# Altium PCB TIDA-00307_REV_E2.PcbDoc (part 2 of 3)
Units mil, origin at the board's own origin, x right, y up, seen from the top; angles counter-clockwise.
Board outline 2360 x 3725 mil, 4 copper layers (Top Layer, L2_GND-PLANE, L3_PWR-PLANE, Bottom Layer), stack 90 mil thick; 312 components, 149 nets, 674 pads, 257 vias.
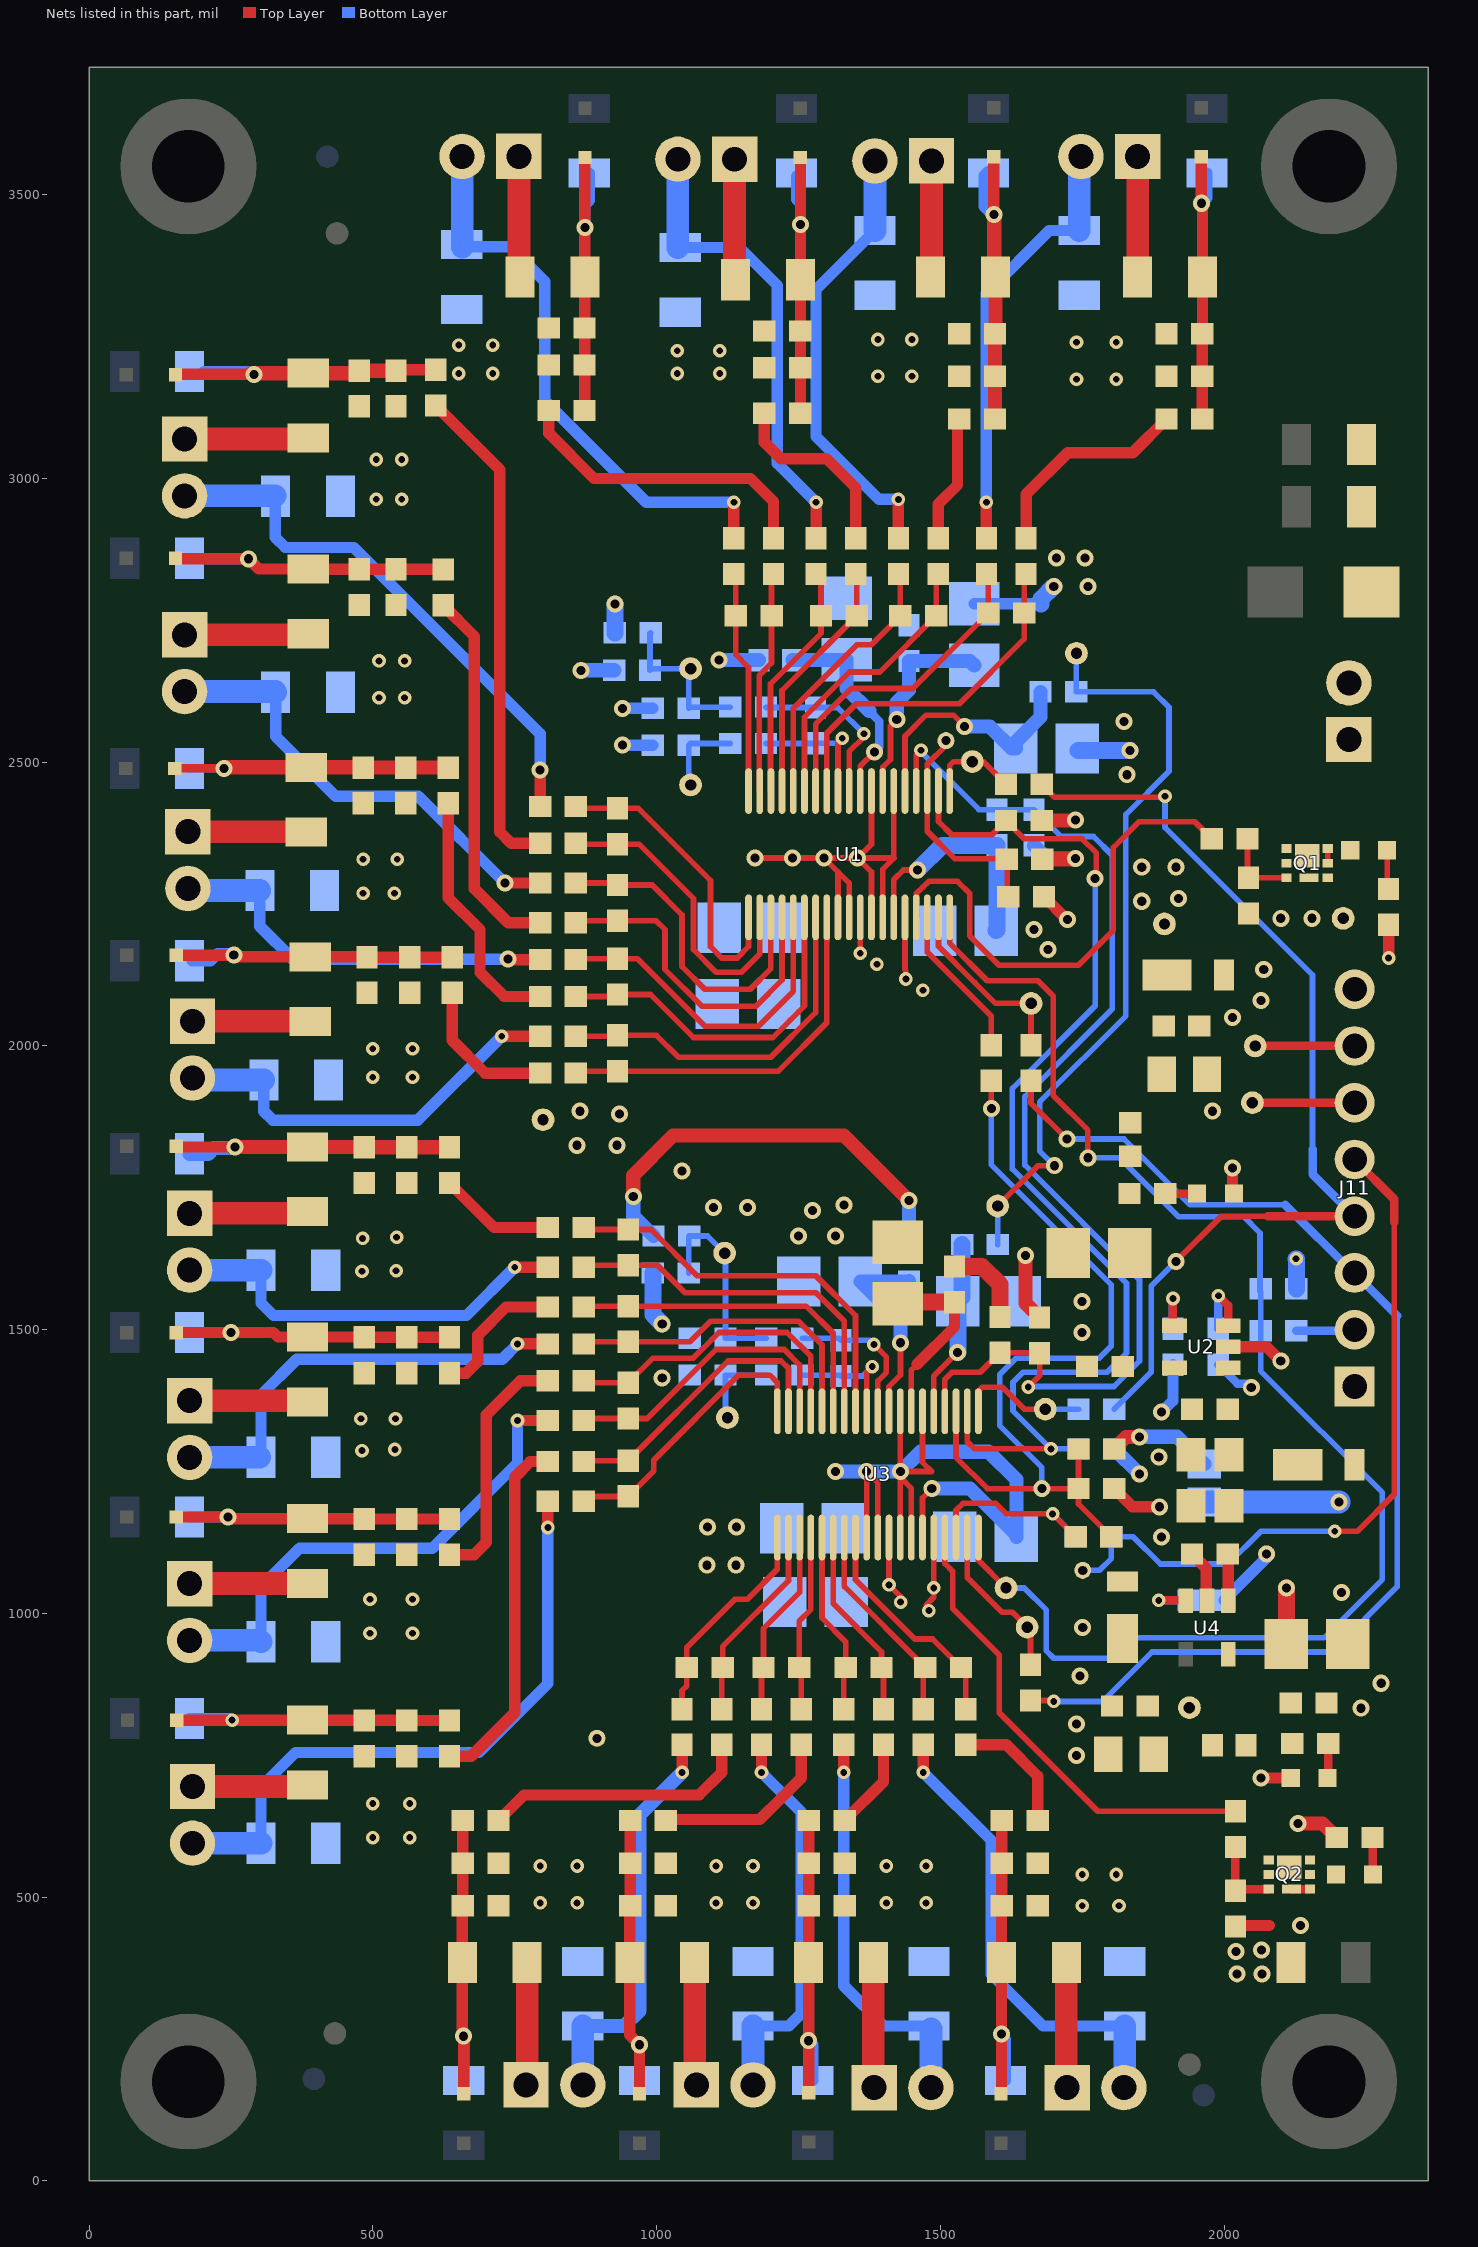
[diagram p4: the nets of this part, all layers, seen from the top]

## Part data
C1 C2: "CAP, CERM, 1000pF, 2KV 10% X7R 1206"
C3 C4 C5 C6 C7 C8 C10 C12 C14 C17 C20 C22 C26 C27 C28 C29 C45 C56: "CAP, CERM, 0.01uF, 100V, +/-5%, X7R, 0603"
C9 C34: "CAP, CERM, 0.1uF, 25V, +/-5%, X7R, 0603"
C11 C19 C21 C25 C31 C32: "CAP, CERM, 0.1uF, 50V, +/-10%, X7R, 0603"
C13 C33: "CAP, CERM, 4.7uF, 50V, +/-10%, X5R, 0805"
C15 C43: "CAP, CERM, 1uF, 16V, +/-10%, X7R, 0603"
C16 C18 C30 C41 C42 C46 C48 C49 C50 C52 C54 C58 C59 C60: library part 293D106X9016B2TE3, "CAP, TA, 10 µF, 16 V, +/- 10%, 2 ohm, SMD"
C23 C24: "CAP, CERM, 1uF, 50V, +/-10%, X7R, 0805"
C35 C36 C37 C38 C39 C40 C44 C47 C51 C53 C57 C61 C62 C63 C64 C65: "CAP, CERM, 0.027uF, 50V, +/-5%, C0G/NP0, 1206"
C55: "CAP, CERM, 0.01uF, 50V, +/-5%, X7R, 0603"
D1 D2 D3 D4 D5 D6 D8 D10 D12 D14 D16 D18 D21 D22 D23 D24: library part CDSOD323-T15SC, "Diode, TVS, ARRAY, 19V, SOD323"
D7: "TVS 18 VOLT 600 WATT BI-DIR SMB"
D9 D13 D19 D20: "LED SmartLED Green 570NM"
D11 D17: "DIODE ZENER 5.9V 1W PMDS"
D15: "Diode, Schottky, 200V, 1A, PowerDI123"
FB1 FB2 FB3 FB4: library part MMZ1608B102C, "FERRITE CHIP 1000 OHM 300MA 0603"
FID1 FID2 FID3 FID4 FID5 FID6: library part Fiducial40_0
H1 H2 H3 H4: "Machine Screw, Round, #4-40 x 1/4, Nylon, Philips panhead"
J1 J2 J3 J4 J5 J6 J7 J8 J9 J10 J12 J13 J14 J15 J16 J17 J18: "Terminal Block, 4x1, 2.54mm, TH"
J11: "Terminal Block, 8x1, 2.54 mm, TH"
LBL1: library part THT-14-423-10, "Thermal Transfer Printable Labels, 0.650\" W x 0.200\" H - 10,000 per roll"
Logo1: library part TI_Logo, "Texas Instrument Corporate Signature"
Q1 Q2: "MOSFET, N-CH, 30V, 22A, SON 2X2 MM"
R1 R2 R3 R4 R19 R29 R36 R48 R57 R69 R80 R94 R111 R112 R113 R114: "RES 100 OHM .4W 1% 0204 MELF"
R5 R6 R7 R8 R9 R11 R13 R15 R17 R20 R30 R32 R37 R42 R52 R53 R59 R60 R71 R72 R81 R82 R95 R96 R102 R103 R104 R105 R107 R108 R109 R110: library part CRCW060322R0JNEA, "RES, 22 ohm, 1%, 0.1W, 0603"
R10 R12 R14 R16 R18 R31 R38 R49 R61 R73 R78 R83 R97 R98 R99 R100: "RES, 1.00k ohm, 1%, 0.1W, 0603"
R21 R23 R24 R26 R33 R44 R46 R50 R63 R66 R70 R74 R85 R87 R89 R91: "RES, 1.6k ohm, 5%, 0.1W, 0603"
R22 R25 R27 R28 R34 R39 R43 R51 R54 R55 R56 R62 R64 R65 R75 R79 R84 R86 R88 R90 R92 R123 R124 R127 R131 R134 R135 R138 R140 R143: library part RC0402JR-070RL, "RES, 0 ohm,5%, 0.1W, 0603"
R35 R40 R45 R67 R68 R76 R77 R126 R128 R133 R142 R154 R155 R156 R157: library part RT0603BRD0747KL, "RES, 47.0k ohm, 1%, 0.1W, 0603"
R41 R47 R101 R106: "RES, 300 ohm, 5%, 0.1W, 0603"
R58 R93: "RES, 560 ohm, 5%, 0.1W, 0603"
R115 R116 R117 R118 R119 R120 R121 R129 R130 R132 R141 R146 R147 R148 R149 R150 R151: library part RC0402JR-070RL, "RES, 0 ohm,5%, 0.25W, 1206"
R122 R125 R136 R139: "RES, 357 ohm, 1%, 0.1W, 0603"
R137 R145: "RES, 10.0k ohm, 1%, 0.1W, 0603"
R144: library part RC0402JR-070RL, "RES, 0 ohm,5%, 0.125W, 0805"
TP1 TP2 TP3 TP4 TP5 TP6 TP7 TP8 TP9 TP10 TP11 TP12 TP13 TP14 TP15 TP16 TP17 TP18 TP19 TP20 TP21 TP22 TP23 TP24: library part TP-040_RND, "Test Point 40mil pad 20mil drill"
U1 U3: "16 bit 400KSPS 8 Channel SAR ADC"
U2: "IC REG LDO 5V 0.15A SOT23-5"
U4: "IC REG LDO 3.3V 0.15A SOT23-5"
ZZ1: library part AssemblyNoteLabel
ZZ2 ZZ3 ZZ4: library part AssemblyNote

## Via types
v1: diameter 30, hole 16, Top Layer to Bottom Layer, tented both sides, 155 vias
v2: diameter 24, hole 12, Top Layer to Bottom Layer, tented both sides, 102 vias

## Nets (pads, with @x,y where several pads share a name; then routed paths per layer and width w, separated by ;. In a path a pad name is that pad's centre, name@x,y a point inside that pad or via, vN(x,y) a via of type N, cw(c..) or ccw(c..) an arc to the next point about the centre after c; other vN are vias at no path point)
2AIN0: R65.1 R78.2 | length 482.3
  Top Layer w20: R78.2@635,1103.5 678.5,1103.5 700,1125 ; 700,1175 700,1125 ; R65.1@808.5,1410 760,1410 700,1350 700,1125
2AIN1: R75.1 R83.2 | length 631.7
  Top Layer w20: R83.2@635,748.5 673.5,748.5 750,825 750,885 750,1240 777.73,1267.73 R75.1@808.5,1267.73
2AIN2: R84.2 R97.2 | length 477.2
  Top Layer w20: R97.2@721.5,635 766.5,680 835,680 875,680 1075,680 1115,720 R84.2@1115,768.5
2AIN3: R86.2 R98.2 | length 328.1
  Top Layer w20: R98.2@1016.5,635 1018.39,636.89 1118.5,636.89 1181.89,636.89 1220,675 1240,695 1255,710 R86.2@1255,768.5
2AIN4: R88.2 R99.2 | length 161.9
  Top Layer w20: R99.2@1331.5,635 1400,703.5 1400,720 R88.2@1400,768.5
2AIN5: R90.2 R100.2 | length 227.8
  Top Layer w20: R90.2@1545,768.5 1616.61,768.5 1671.5,713.62 R100.2@1671.5,635
2AIN6: R61.2 R62.1 | length 252.5
  Top Layer w20: R61.2@635,1758.5 713.5,1680 ; 760,1680 713.5,1680 ; R62.1@808.5,1680 713.5,1680
2AIN7: R64.1 R73.2 | length 275.1
  Top Layer w20: R73.2@635,1423.5 664.77,1423.5 685,1443.73 ; 685,1470 685,1443.73 ; R64.1@808.5,1540 735,1540 685,1490 685,1443.73
2IN_AIN0: J13.1 R80.1 | length 199.9
  Top Layer w40: J13.1@177.32,1052.64 R80.1@377.17,1052.64
2IN_AIN0_N: J13.2 R70.1 R146.2 | length 894.5
  Top Layer w20: v2(755,1340) R70.1@808.5,1340
  Bottom Layer w20: R146.2@302.91,950 302.91,1046.91 371,1115 605,1115 755,1265 v2(755,1340)
  Bottom Layer w40: J13.2@177.32,952.64 300.27,952.64 R146.2@302.91,950
2IN_AIN1: J14.1 R94.1 | length 207.8
  Top Layer w40: J14.1@185.15,697.91 J14.1@182.32,695.09 382.17,695.09 R94.1@385,697.91
2IN_AIN1_N: J14.2 R74.1 R147.2 | length 1124.8
  Top Layer w20: v2(808.5,1151.5) R74.1@808.5,1197.73
  Bottom Layer w20: R147.2@302.91,595 302.91,693.91 364,755 687,755 808.5,876.5 v2(808.5,1151.5)
  Bottom Layer w30: J14.2@180.35,593.12 J14.2@182.32,595.09
  Bottom Layer w40: J14.2@182.32,595.09 182.41,595 R147.2@302.91,595
2IN_AIN2: J15.1 R111.1 | length 216.6
  Top Layer w40: J15.1@770,169.29 772.09,171.38 R111.1@772.09,385
2IN_AIN2_N: J15.2 R85.2 R148.2 | length 714.4
  Top Layer w20: v2(1045,720) R85.2@1045,768.5
  Bottom Layer w25: R148.2@870,272.91 942.91,272.91 970,300 970,645 v2(1045,720)
  Bottom Layer w40: J15.2@870,169.29 R148.2@870,272.91
2IN_AIN3: J16.1 R112.1 | length 213.6
  Top Layer w40: J16.1@1067.09,171.38 R112.1@1067.09,385
2IN_AIN3_N: J16.2 R87.2 R149.2 | length 700.3
  Top Layer w20: v2(1185,720) R87.2@1185,768.5
  Bottom Layer w20: R149.2@1170,272.91 1232.91,272.91 1255,295 1255,650 v2(1185,720)
  Bottom Layer w40: J16.2@1170,169.29 R149.2@1170,272.91
2IN_AIN4: J17.1 R113.1 | length 213.6
  Top Layer w40: J17.1@1382.09,171.38 R113.1@1382.09,385
2IN_AIN4_N: J17.2 R89.2 R150.2 | length 707.6
  Top Layer w20: v2(1330,720) R89.2@1330,768.5
  Bottom Layer w20: v2(1330,720) 1330,344 1401.09,272.91 R150.2@1480,272.91
  Bottom Layer w40: J17.2@1483.5,164.29 R150.2@1483.5,267.91
2IN_AIN5: J18.1 R114.1 | length 213.6
  Top Layer w40: J18.1@1722.09,171.38 R114.1@1722.09,385
2IN_AIN5_N: J18.2 R91.2 R151.2 | length 836.2
  Top Layer w20: v2(1470,720) R91.2@1470,768.5
  Bottom Layer w20: v2(1470,720) 1590,600 1590,364 1681.09,272.91 R151.2@1825,272.91
  Bottom Layer w40: J18.2@1823.5,164.29 1825,165.79 R151.2@1825,272.91
2IN_AIN6: J10.1 R57.1 | length 199.9
  Top Layer w40: J10.1@177.32,1705.09 R57.1@377.17,1705.09
2IN_AIN6_N: J10.2 R63.1 R132.2 | length 733.5
  Top Layer w20: v2(750,1610) R63.1@808.5,1610
  Bottom Layer w20: R132.2@302.91,1605 302.91,1547.09 325,1525 665,1525 v2(750,1610)
  Bottom Layer w40: J10.2@177.32,1605.09 177.41,1605 R132.2@302.91,1605
2IN_AIN7: J12.1 R69.1 | length 199.9
  Top Layer w40: J12.1@177.32,1375.09 R69.1@377.17,1375.09
2IN_AIN7_N: J12.2 R66.1 R141.2 | length 775.8
  Top Layer w20: v2(755,1475) R66.1@808.5,1475
  Bottom Layer w20: R141.2@302.91,1275 302.91,1384.91 366,1448 728,1448 v2(755,1475)
  Bottom Layer w40: J12.2@177.32,1275.09 R141.2@300.27,1275.09
+3.3V: C31.1 C33.1 C49.1 C59.1 D17.1 FB2.2 R47.2 R101.2 R133.1 R144.2 TP20.1 U1.34 U3.34 | length 667.4
  Top Layer w10: U1.34@1437.76,2226.77 1437.76,2134.69 1439.33,2133.11 v2(1439.33,2118.11) v2@1439.33,2113.11 ; v2@1475,1015 1488.43,1028.43 v2(1488.43,1045) U3.34@1488.43,1133.78
  Top Layer w20: v2(2290,2155) R47.2@2290,2213.5
  Top Layer w25: v1(2130,630) 2173.5,630 R101.2@2198.5,605
  Bottom Layer w30: v2(2127,1625) 2127.5,1624.5 R133.1@2127.5,1572
  Bottom Layer w40: R144.2@1965,1196.54 v1(2202.54,1196.54) v1@2203,1197
  other v1: 1746,890 1751,975 860,1825 930,1825 935,1880 865,1885
  other v2: 1480,1005 1469.33,2098.11
+5V: C11.1 C13.1 D11.1 FB1.2 FB3.1 FB4.1 R35.1 R40.1 R68.1 R77.1 R128.1 R142.1 R144.1 R154.2 R156.2 TP5.1 | length 1469.5
  Top Layer w25: v1(959,1735) 959,1772 1029,1842 1330.47,1842 v1(1445,1727.47) ; v1(1650,1631) 1650,1546.5 R68.1@1675,1521.5 ; R35.1@1678.83,2397.11 1737.33,2397.11 v1(1738.33,2398.11) ; R40.1@1679.83,2329.11 1737.33,2329.11 v1(1738.33,2330.11) ; R77.1@1806.5,1290 1827.5,1311 v1(1851,1311)
  Bottom Layer w25: v1(867,2662) R154.2@925.5,2662 ; v1(959,1735) 959,1700.5 R156.2@994.5,1665 ; v1(1110,2680) FB3.1@1180.47,2680 ; FB4.1@1445,1644.53 v1(1445,1727.47) ; R128.1@1665,2353.5 1688.39,2330.11 v1(1738.33,2330.11) ; R142.1@1806.5,1290 v1(1851,1245.5) v1@1851,1244 ; v1(1851,1311) 1851.5,1311.5 1916.96,1311.5 R144.1@1965,1263.46
  other v1: 1855,2255 1920,2260 1855,2315 1915,2315
+5V_AVDD: C41.1 C48.1 C50.1 C52.1 C58.1 C60.1 FB3.2 FB4.2 U1.9 U1.30 U3.9 U3.30 | length 894.2
  Top Layer w10: U1.30@1359.02,2226.77 v2(1359.02,2163.43) v2@1359.33,2163.11 ; U1.9@1359.02,2449.21 1359.02,2493.11 1384.02,2518.11 v1(1384.33,2518.11) ; U3.30@1409.69,1133.78 v2(1409.69,1050.31) v2@1430,1030 ; U3.9@1409.69,1356.22 1409.69,1399.69 1430,1420 v1(1430,1477)
  Bottom Layer w15: 1374.83,2590 1392.83,2572 1392.83,2526.61 v1(1384.33,2518.11)
  Bottom Layer w25: FB3.2@1239.53,2680 1334.13,2680 C41.1@1335,2680.87 1335,2629.83 1374.83,2590 ; v1(1430,1477) 1430,1514.13 C52.1@1359.13,1585 1444.53,1585 FB4.2@1445,1585.47
  other v2: 1430,1020 1388.33,2144.11
+DC_IN: C21.1 C23.1 C24.1 C25.1 D15.1 R137.2 R145.2 TP15.1 U2.1 U4.1 | length 270.5
  Top Layer w20: C25.1@2006.5,1105 2007.4,1104.09 U4.1@2007.4,1022.24
  Bottom Layer w15: R137.2@1990,1438.5 2023.5,1405 2040.89,1405 v1(2048,1397.89)
  Bottom Layer w20: R145.2@2000.31,1023.43 2075,1098.13 TP15.1@2075,1105
/CS0: R133.2 R138.2 TP16.1 U1.38 U3.38 | length 2558.2
  Top Layer w10: U1.38@1516.5,2226.77 1516.5,2181.4 1582.9,2115 1672,2115 1699,2088 1699,1913 1760,1852 v1(1760,1803) ; U3.38@1567.17,1133.78 1567.17,1093.75 TP16.1@1615.91,1045
  Bottom Layer w10: TP16.1@1615.91,1045 1648,1045 1687,1006 1687,934 1700,921 1807.6,921 1843.6,957 2176,957 2279,1060 2279,1213 2064.5,1427.5 R138.2@2064.5,1498 2064.5,1567 2063.5,1568 2063.5,1670.5 2035,1699 1920,1699 1816,1803 v1(1760,1803)
\R\E\F\S\E\L\: R67.1 R68.2 R126.1 R128.2 U1.4 U3.4 | length 2054.9
  Top Layer w10: U1.4@1457.44,2449.21 1457.44,2512.44 v2(1466,2521) ; U3.4@1508.11,1356.22 1508.11,1412.65 1520.46,1425 1570.55,1425 R67.1@1605,1459.45 1674.06,1459.45 R68.2@1675,1458.5 1675,1419 v2(1655,1399)
  Bottom Layer w10: v2(1466,2521) 1466,2518.44 1567.94,2416.5 R126.1@1600,2416.5 R128.2@1665,2416.5 1712.5,2369 1770,2369 1803,2336 1803,2065 1649,1911 1649,1790 1851,1588 1851,1445 1806,1400 1656,1400 v2(1655,1399)
\R\S\T\/\P\D\: R35.2 R142.2 U1.2 U3.2 | length 2022.5
  Top Layer w10: U1.2@1496.81,2449.21 1496.81,2395.63 1520.33,2372.11 1590.83,2372.11 R35.2@1615.83,2397.11 1647.95,2365 1750,2365 1775,2340 1775,2297 v1(1773,2295) ; U3.2@1547.48,1356.22 1547.48,1302.52 1560,1290 v2(1695,1290)
  Bottom Layer w10: R142.2@1743.5,1290 v2(1695,1290) 1628,1357 1628,1407.36 1645.64,1425 1794,1425 1828,1459 1828,1582 1627,1783 1627,1925 1773,2071 v1(1773,2295)
AIN0: R12.2 R25.1 | length 334.2
  Top Layer w20: R12.2@1190,3115 1190,3064 1219,3035 1299.33,3035 1351.22,2983.11 R25.1@1351.22,2894.61
AIN1: R10.2 R22.1 | length 550.8
  Top Layer w20: R10.2@810,3120 810,3080 890,3000 1165.4,3000 1206.22,2959.18 R22.1@1206.22,2894.61
AIN2: R18.2 R39.2 | length 877.4
  Top Layer w20: R18.2@611,3128.5 724,3015.5 724,2377 743.8,2357.2 R39.2@794.84,2357.2
AIN3: R31.2 R43.2 | length 662.9
  Top Layer w20: R31.2@624,2776.5 679,2721.5 679,2277 738.8,2217.2 R43.2@794.84,2217.2
AIN4: R38.2 R51.2 | length 444.3
  Top Layer w20: R38.2@633,2427.5 633,2261 689,2205 689,2130 731.8,2087.2 R51.2@794.84,2087.2
AIN5: R49.2 R54.2 | length 262.3
  Top Layer w20: R49.2@640,2093.5 640,2010 697.8,1952.2 R54.2@794.84,1952.2
AIN6: R16.2 R28.1 | length 379.9
  Top Layer w20: R28.1@1651.22,2894.61 1651.22,2972.22 1724.5,3045.5 1839,3045.5 R16.2@1898.5,3105
AIN7: R14.2 R27.1 | length 225.8
  Top Layer w20: R27.1@1496.22,2894.61 1496.22,2954.61 1530.31,2988.69 1530.31,3101.8 R14.2@1533.5,3105
DAIAG: R122.1 R123.2 R154.1 R155.2 TP1.1 | length 284.8
  Bottom Layer w10: R155.2@989.5,2728 988.5,2727 R154.1@988.5,2662 991.5,2665 TP1.1@1060,2665 1056.5,2661.5 R123.2@1056.5,2595 1058.61,2597.11 R122.1@1129.83,2597.11
DAIAG1: R135.2 R136.1 R156.1 R157.2 TP12.1 | length 363
  Bottom Layer w10: R157.2@1056.5,1600 1056.5,1664 R156.1@1057.5,1665 1090,1665 TP12.1@1120,1635 1121.5,1633.5 R135.2@1121.5,1485 R136.1@1193.5,1485
DAISY: R40.2 R45.2 TP23.1 U1.3 | length 402.4
  Top Layer w10: TP23.1@1510,2538 1510,2529.64 1477.13,2496.77 U1.3@1477.13,2449.21 1477.13,2378.32 1525.33,2330.11 1616.83,2330.11 1617.83,2329.11 R45.2@1617.83,2261.11
GND_EARTH: C1.2 C2.2 D7.2 J7.1 J7.2
I2C_SCL: J11.7 TP8.1 | length 175
  Top Layer w15: TP8.1@2055,2000 J11.7@2230,2000
I2C_SDA: J11.6 TP10.1 | length 180
  Top Layer w15: TP10.1@2050,1900 J11.6@2230,1900
IN_AIN0: J2.1 R2.1 | length 215.6
  Top Layer w40: R2.1@1137.5,3346.91 J2.1@1137.5,3562.56
IN_AIN0_N: J2.2 R23.1 R119.2 | length 832.4
  Top Layer w20: R23.1@1281.22,2894.61 v2(1281.22,2958.11)
  Bottom Layer w20: R119.2@1037.5,3407.09 R119.2@1041.5,3407.09 1145.91,3407.09 1213,3340 1213,3026.33 v2(1281.22,2958.11)
  Bottom Layer w40: R119.2@1037.5,3407.09 J2.2@1037.5,3562.56
IN_AIN1: J1.1 R1.1 | length 215.6
  Top Layer w40: R1.1@757.5,3351.91 J1.1@757.5,3567.56
IN_AIN1_N: J1.2 R21.1 R118.2 | length 1011.1
  Top Layer w20: R21.1@1136.22,2894.61 v2(1136.22,2958.11)
  Bottom Layer w20: R118.2@657.5,3408.09 741.91,3408.09 803,3347 803,3137 981.89,2958.11 v2(1136.22,2958.11)
  Bottom Layer w40: R118.2@657.5,3408.09 J1.2@657.5,3567.56
IN_AIN2: J5.1 R19.1 | length 215.6
  Top Layer w40: J5.1@168.44,3069.5 R19.1@384.09,3069.5
IN_AIN2_N: J5.2 R33.2 R120.2 | length 970.9
  Top Layer w20: R33.2@794.84,2422.2 794.84,2485.84 v1(795,2486)
  Bottom Layer w20: R120.2@327.91,2969.5 327.91,2896.58 346,2878.5 466.5,2878.5 795,2550 v1(795,2486)
  Bottom Layer w40: J5.2@168.44,2969.5 R120.2@327.91,2969.5
IN_AIN3: J6.1 R29.1 | length 218.4
  Top Layer w40: J6.1@168.44,2724.5 384.09,2724.5 R29.1@386,2726.41
IN_AIN3_N: J6.2 R44.2 R121.2 | length 811.9
  Top Layer w20: v1(733,2287) 733.2,2287.2 R44.2@794.84,2287.2
  Bottom Layer w20: R121.2@328.91,2623.5 328.91,2545.58 434.5,2440 580,2440 v1(733,2287)
  Bottom Layer w40: J6.2@168.44,2624.5 327.91,2624.5 R121.2@328.91,2623.5
IN_AIN4: J8.1 R36.1 | length 199.9
  Top Layer w40: J8.1@174.26,2377.59 R36.1@374.11,2377.59
IN_AIN4_N: J8.2 R46.2 R129.2 | length 709.4
  Top Layer w20: v1(738,2153) 738.8,2152.2 R46.2@794.84,2152.2
  Bottom Layer w20: R129.2@300.91,2274 300.91,2211.09 359,2153 v1(738,2153)
  Bottom Layer w40: J8.2@174.26,2277.59 177.85,2274 R129.2@300.91,2274
IN_AIN5: J9.1 R48.1 | length 199.9
  Top Layer w40: J9.1@182.32,2043.59 R48.1@382.17,2043.59
IN_AIN5_N: J9.2 R50.2 R130.2 | length 737
  Top Layer w20: v2(727.2,2017.2) R50.2@794.84,2017.2
  Bottom Layer w20: R130.2@307.91,1940 307.91,1885.09 324,1869 579,1869 v2(727.2,2017.2)
  Bottom Layer w40: J9.2@182.32,1943.59 185.91,1940 R130.2@307.91,1940
IN_AIN6: J4.1 R4.1 | length 199.9
  Top Layer w40: R4.1@1847.87,3367.45 J4.1@1847.87,3567.3
IN_AIN6_N: J4.2 R26.1 R117.2 | length 772.7
  Top Layer w20: R26.1@1581.22,2894.61 v2(1581.22,2958.11)
  Bottom Layer w20: v2(1581.22,2958.11) 1581.22,3326.22 1692.09,3437.09 R117.2@1745,3437.09
  Bottom Layer w40: R117.2@1745,3437.09 1745,3564.43 J4.2@1747.87,3567.3
IN_AIN7: J3.1 R3.1 | length 199.9
  Top Layer w40: R3.1@1484.59,3359.83 J3.1@1484.59,3559.68
IN_AIN7_N: J3.2 R24.1 R116.2 | length 788.6
  Top Layer w20: R24.1@1426.22,2894.61 v2(1426.22,2963.11)
  Bottom Layer w20: R116.2@1385,3437.09 1281,3333.09 1281,3074 1391.89,2963.11 v2(1426.22,2963.11)
  Bottom Layer w40: J3.2@1384.59,3559.68 1385,3559.26 R116.2@1385,3437.09
LED1: R41.1 U1.35 | length 880.2
  Top Layer w10: U1.35@1457.44,2226.77 1458.22,2227.55 1458.22,2269.05 1469.3,2280.13 1469.72,2280.13 1479.6,2290 1530.4,2290 1552,2268.4 1552,2194 1604,2142 1743,2142 1805,2204 1805,2350 1850,2395 1948.5,2395 R41.1@1978.5,2365 R41.1@1979.18,2365.68
LED2: R106.1 U3.35 | length 836.4
  Top Layer w10: U3.35@1508.11,1133.78 1508.11,1088 1522,1074.11 1522,1008.54 1604,926.54 1604,825 1777.5,651.5 R106.1@2020,651.5
NetC3_1: C3.1 R22.2 U1.18 | length 393.1
  Top Layer w10: U1.18@1181.85,2449.21 1181.07,2449.99 1181.07,2652.96 1202.72,2674.61 C3.1@1202.72,2758.11 1202.72,2828.11 R22.2@1206.22,2831.61
NetC3_2: C3.2 R21.2 U1.19 | length 393.1
  Top Layer w10: R21.2@1136.22,2831.61 1139.72,2828.11 C3.2@1139.72,2758.11 1139.72,2689.61 1162.17,2667.17 U1.19@1162.17,2449.21
NetC4_1: C4.1 R25.2 U1.16 | length 437.5
  Top Layer w10: U1.16@1221.22,2449.21 1221.22,2626.61 C4.1@1352.72,2758.11 1352.72,2830.12 R25.2@1351.22,2831.61
NetC4_2: C4.2 R23.2 U1.17 | length 423.1
  Top Layer w10: U1.17@1201.54,2449.21 1200.76,2449.99 1200.76,2638.03 1289.72,2727 C4.2@1289.72,2758.11 1289.72,2823.11 R23.2@1281.22,2831.61
NetC5_1: C5.1 R27.2 U1.14 | length 511.3
  Top Layer w10: U1.14@1260.59,2449.21 1260.59,2579.41 1340.18,2659 1393.61,2659 C5.1@1492.72,2758.11 1492.72,2828.11 R27.2@1496.22,2831.61
NetC5_2: C5.2 R24.2 U1.15 | length 477.1
  Top Layer w10: U1.15@1240.91,2449.21 1240.91,2594.91 1353,2707 1378.61,2707 C5.2@1429.72,2758.11 1429.72,2828.11 R24.2@1426.22,2831.61
NetC6_1: C6.1 R28.2 U1.12 | length 634.3
  Top Layer w10: U1.12@1299.96,2449.21 1299.96,2550.96 1352,2603 1533.72,2603 1647.72,2717 C6.1@1647.72,2763.11 1647.72,2828.11 R28.2@1651.22,2831.61
NetC6_2: C6.2 R26.2 U1.13 | length 573.6
  Top Layer w10: U1.13@1280.28,2449.21 1280.28,2567.28 1343,2630 1451.61,2630 C6.2@1584.72,2763.11 1584.72,2828.11 R26.2@1581.22,2831.61
NetC7_1: C7.1 R39.1 U1.21 | length 548.8
  Top Layer w10: R39.1@857.83,2357.2 859.33,2355.71 C7.1@931.34,2355.71 969,2355.71 1065,2259.71 1065,2170 1105,2130 1150,2130 1181.85,2161.85 U1.21@1181.85,2226.77
NetC7_2: C7.2 R33.1 U1.20 | length 543.4
  Top Layer w10: R33.1@857.83,2422.2 861.34,2418.7 C7.2@931.34,2418.7 968,2418.7 1095,2291.7 1095,2175 1115,2155 1142.17,2155 1162.17,2175 U1.20@1162.17,2226.77
NetC8_1: C8.1 R43.1 U1.23 | length 656.7
  Top Layer w10: R43.1@857.83,2217.2 861.34,2220.71 C8.1@931.34,2220.71 999.29,2220.71 1015,2205 1015,2135 1080,2070 1175,2070 1221.22,2116.22 ; 1221.22,2175 1221.22,2116.22 ; U1.23@1221.22,2226.77 1221.22,2116.22
NetC8_2: C8.2 R44.1 U1.22 | length 575
  Top Layer w10: R44.1@857.83,2287.2 C8.2@927.83,2287.2 ; C8.2@931.34,2283.7 992.3,2283.7 1045,2231 1045,2140 1085,2100 1165,2100 1201.54,2136.54 U1.22@1201.54,2226.77
NetC9_1: C9.1 Q1.3 R41.2 | length 205.7
  Top Layer w10: R41.2@2040,2370.5 2041.5,2369.01 C9.1@2041.5,2298 ; C9.1@2041.5,2297 C9.1@2041.5,2298 ; R41.2@2041.5,2365 C9.1@2041.5,2298 ; C9.1@2043,2296.5 C9.1@2041.5,2298 ; C9.1@2047.81,2297 2048.41,2296.41 Q1.3@2110,2296.41
NetC10_1: C10.1 R51.1 U1.25 | length 609.8
  Top Layer w10: R51.1@857.83,2087.2 C10.1@927.83,2087.2 ; C10.1@931.34,2090.71 989.29,2090.71 1065,2015 1205,2015 1235,2045 1250,2060 1260.59,2070.59 1260.59,2099.85 U1.25@1260.59,2226.77
NetC10_2: C10.2 R46.1 U1.24 | length 589
  Top Layer w10: R46.1@857.83,2152.2 859.33,2153.7 C10.2@931.34,2153.7 966.3,2153.7 1085,2035 1180,2035 1240.91,2095.91 U1.24@1240.91,2226.77
NetC12_1: C12.1 R54.1 U1.27 | length 707.3
  Top Layer w10: R54.1@857.83,1952.2 861.34,1955.71 C12.1@931.34,1955.71 1214.67,1955.71 1299.96,2041 U1.27@1299.96,2226.77 1300.74,2225.99 1300.74,2184.49
NetC12_2: C12.2 R50.1 U1.26 | length 637.5
  Top Layer w10: R50.1@857.83,2017.2 C12.2@929.84,2017.2 ; C12.2@931.34,2018.7 1000,2018.7 1038.7,1980 1201.28,1980 1280.28,2059 U1.26@1280.28,2226.77
NetC14_1: C14.1 R62.2 U3.12 | length 712.1
  Top Layer w10: R62.2@871.5,1680 875,1676.5 C14.1@950,1676.5 990,1676.5 1071.5,1595 1280.63,1595 1350.63,1525 U3.12@1350.63,1356.22
NetC14_2: C14.2 R63.2 U3.13 | length 660.5
  Top Layer w10: R63.2@871.5,1610 875,1613.5 C14.2@950,1613.5 1001.5,1613.5 1050,1565 1280.94,1565 1330.94,1515 U3.13@1330.94,1356.22
NetC15_2: C15.2 C18.1 U3.7 | length 324.8
  Top Layer w10: U3.7@1449.06,1356.22 1449.06,1429.06 1459,1439
  Top Layer w20: 1459,1439 1525,1505 C15.2@1525,1548.5
  Top Layer w30: C18.1@1425,1545.87 1427.64,1548.5 C15.2@1525,1548.5
NetC16_1: C16.1 C19.1 FB1.1 R58.2 U2.5
NetC17_1: C17.1 R64.2 U3.14 | length 597.7
  Top Layer w10: R64.2@871.5,1540 872.99,1541.5 C17.1@950,1541.5 1263.5,1541.5 1311.26,1493.74 U3.14@1311.26,1356.22
NetC17_2: C17.2 R66.2 U3.15 | length 571.1
  Top Layer w10: R66.2@871.5,1475 875,1478.5 C17.2@950,1478.5 1058.5,1478.5 1095,1515 1250,1515 1291.57,1473.43 U3.15@1291.57,1356.22
NetC20_1: C20.1 R65.2 U3.16 | length 552.7
  Top Layer w10: R65.2@871.5,1410 875,1406.5 C20.1@950,1406.5 993.5,1450 1064.54,1450 1097.54,1483 1098,1483 1110,1495 1230,1495 1271.89,1453.11 U3.16@1271.89,1356.22
NetC20_2: C20.2 R70.2 U3.17 | length 525.3
  Top Layer w10: R70.2@871.5,1340 875,1343.5 C20.2@950,1343.5 983.5,1343.5 1105,1465 1225,1465 1252.2,1437.8 U3.17@1252.2,1356.22
NetC22_1: C22.1 R75.2 U3.18 | length 515.6
  Top Layer w10: R75.2@871.5,1267.73 872.99,1269.23 C22.1@950.02,1269.23 1125.79,1445 1219.54,1445 1232.52,1432.02 U3.18@1232.52,1356.22
NetC22_2: C22.2 R74.2 U3.19 | length 500.7
  Top Layer w10: R74.2@871.5,1197.73 880,1206.24 C22.2@950.02,1206.24 995,1251.22 995,1270 1145,1420 1200,1420 1212.83,1407.17 U3.19@1212.83,1356.22
NetC26_1: C26.1 R84.1 U3.21 | length 351
  Top Layer w10: R84.1@1115,831.5 1115,903.5 C26.1@1116.5,905 1116.5,941.5 1232.52,1057.52 U3.21@1232.52,1133.78
NetC26_2: C26.2 R85.1 U3.20 | length 384.7
  Top Layer w10: R85.1@1045,831.5 1045,864 1053.5,872.5 C26.2@1053.5,905 1053.5,940.5 1138,1025 1160,1025 1212.83,1077.83 U3.20@1212.83,1133.78
NetC27_1: C27.1 R86.1 U3.23 | length 312.2
  Top Layer w10: R86.1@1255,831.5 1255,901.5 C27.1@1251.5,905 1251.5,986.5 1271.89,1006.89 U3.23@1271.89,1133.78
NetC27_2: C27.2 R87.1 U3.22 | length 330.1
  Top Layer w10: R87.1@1185,831.5 1185,901.5 C27.2@1188.5,905 1188.5,973.5 1252.2,1037.2 U3.22@1252.2,1133.78
NetC28_1: C28.1 R88.1 U3.25 | length 349
  Top Layer w10: U3.25@1311.26,1133.78 1311.26,1017.44 1396.5,932.2 C28.1@1396.5,915 ; C28.1@1396.5,905 C28.1@1396.5,915 ; R88.1@1400,831.5 1400,911.5 C28.1@1396.5,915
NetC28_2: C28.2 R89.1 U3.24 | length 321.1
  Top Layer w10: U3.24@1291.57,1133.78 1291.57,991.93 1333.5,950 C28.2@1333.5,905 1330,901.5 R89.1@1330,831.5
NetC29_1: C29.1 R90.1 U3.27 | length 401.2
  Top Layer w10: U3.27@1350.63,1133.78 1350.63,1059.37 1455,955 1486.5,955 C29.1@1536.5,905 1545,896.5 R90.1@1545,831.5
NetC29_2: C29.2 R91.1 U3.26 | length 362.8
  Top Layer w10: U3.26@1330.94,1133.78 1330.94,1047.56 C29.2@1473.5,905 1470,901.5 R91.1@1470,831.5
NetC30_1: C30.1 C32.1 FB2.1 R93.2 TP17.1 U4.5 | length 99.1
  Top Layer w30: C30.1@2109.87,946 2109.87,1044.87 TP17.1@2110,1045
NetC34_1: C34.1 Q2.3 R106.2 | length 136.9
  Top Layer w15: R106.2@2020,588.5 C34.1@2020,511.5 2022.91,514.41 Q2.3@2078.68,514.41
NetC35_1: C35.1 D1.1 R1.2 R5.2 R6.2 R10.1 | length 543.5
  Top Layer w20: R10.1@872.99,3120 873.58,3120.59 R1.2@873.58,3355 v1(873.58,3442.09) D1.1@873.58,3564.11
  Bottom Layer w20: v1(873.58,3442.09) 873.58,3482.09 881.5,3490 C35.1@881.5,3537.91
NetC36_1: C36.1 D2.1 R2.2 R7.2 R11.2 R12.1 | length 532.8
  Top Layer w20: R12.1@1252.99,3115 1253.58,3115.59 1253.58,3195 R2.2@1253.58,3350 v1(1253.58,3447.91) D2.1@1253.58,3559.61
  Bottom Layer w20: C36.1@1246.5,3532.91 1246.5,3492 1253.58,3484.91 v1(1253.58,3447.91)
NetC37_1: C37.1 D3.1 R3.2 R8.2 R13.2 R14.1 | length 544.4
  Top Layer w20: D3.1@1594,3566.69 1594,3466 v1(1595,3465)
  Top Layer w25: v1(1595,3465) 1595,3357.09 R3.2@1597.09,3355 1597.09,3255.59 R8.2@1596.5,3255 R13.2@1596.5,3180 R14.1@1596.5,3105
  Bottom Layer w25: C37.1@1585,3537.91 1580,3532.91 1580,3480 v1(1595,3465)
NetC38_1: C38.1 D4.1 R4.2 R9.2 R15.2 R16.1 | length 519.9
  Top Layer w20: D4.1@1960,3566.69 1960,3508.45 v1(1960,3485) 1962.09,3482.91 R4.2@1962.09,3355 1962.09,3255.59 R9.2@1961.5,3255 R15.2@1961.5,3180 R16.1@1961.5,3105
  Bottom Layer w20: v1(1960,3485) 1970,3495 C38.1@1970,3537.91
NetC39_1: C39.1 D5.1 R17.2 R18.1 R19.2 R20.2 | length 554.1
  Top Layer w20: D5.1@157.31,3183.5 v1(291,3183.5) v1@286,3188.5 ; R20.2@541,3189.99 542.5,3191.5 R18.1@611,3191.5
  Top Layer w25: v1(291,3183.5) 293.09,3185.58 R19.2@386,3185.58 471.59,3185.58 R17.2@476,3189.99 R20.2@541,3189.99
  Bottom Layer w20: 203.09,3188.5 286,3188.5 v1(291,3183.5)
NetC40_1: C40.1 D6.1 R29.2 R30.2 R31.1 R32.2 | length 557.9
  Top Layer w20: D6.1@152.31,2859.5 153.31,2858.5 v1(281,2858.5) 298.91,2840.58 R29.2@386,2840.58 386.59,2839.99 R30.2@476,2839.99 R32.2@541,2839.99 623.5,2839.99 R31.1@624,2839.5
  Bottom Layer w20: 203.09,2858.5 v1(281,2858.5)
NetC42_1: C42.1 C43.2 U1.7 | length 366.8
  Top Layer w10: U1.7@1398.39,2449.21 1398.39,2488.11 1399.17,2488.89 1399.17,2491.49 1412.33,2504.66 1412.33,2537.11 1412.33,2564 v1(1423.33,2575)
  Bottom Layer w25: v1(1423.33,2575) 1423.33,2605.44 1445,2627.11 C43.2@1445,2678.5 1552.36,2678.5 C42.1@1560,2670.87
NetC44_1: C44.1 D8.1 R36.2 R37.2 R38.1 R42.2 | length 545.7
  Top Layer w15: D8.1@151.31,2489 v1(238,2489)
  Top Layer w25: v1(238,2489) 240.09,2491.09 R36.2@383,2491.09 482.41,2491.09 R37.2@483,2490.5 R42.2@558,2490.5 R38.1@633,2490.5
  Bottom Layer w15: C44.1@175.09,2489 v1(238,2489)
NetC45_1: C45.1 R122.2 U1.10 | length 300.6
  Top Layer w10: U1.10@1339.33,2449.21 1339.33,2518.76 1365.33,2544.76 v2@1365.33,2547.11
  Bottom Layer w10: R122.2@1192.83,2597.11 1193.44,2596.5 C45.1@1280,2596.5 1318.94,2596.5 v2(1365.33,2550.11)
NetC45_2: C45.2 R125.2 U1.11 | length 234.3
  Top Layer w10: U1.11@1319.65,2449.21 1319.65,2534.43 v2(1327.33,2542.11)
  Bottom Layer w10: R125.2@1192.83,2533.11 1279.61,2533.11 C45.2@1280,2533.5 1318.72,2533.5 v2(1327.33,2542.11)
NetC46_1: C46.1 R127.2 U1.5 | length 449.6
  Top Layer w10: U1.5@1437.76,2449.21 1437.76,2545.76 1474.99,2582.99 1523.01,2582.99 v1(1543,2563)
  Bottom Layer w25: v1(1543,2563) 1587,2563 1626,2524 C46.1@1632.87,2524 1632.87,2535.87 1676.5,2579.5 R127.2@1676.5,2624
NetC47_1: C47.1 D10.1 R48.2 R49.1 R52.2 R53.2 | length 567.7
  Top Layer w20: D10.1@153.31,2160 v1(255,2160) 257.91,2157.09 R48.2@390,2157.09 489.41,2157.09 R52.2@490,2156.5 R53.2@565,2156.5 R49.1@640,2156.5
  Bottom Layer w20: C47.1@182.09,2150 214,2150 227,2163 252,2163 v1(255,2160)
NetC51_1: C51.1 D12.1 R57.2 R59.2 R60.2 R61.1 | length 567.3
  Top Layer w20: D12.1@153.31,1823 154.22,1822.09 v1(257.09,1822.09)
  Top Layer w25: v1@255,1820 v1(257.09,1822.09) R57.2@385,1822.09 484.41,1822.09 R59.2@485,1821.5 R60.2@560,1821.5 R61.1@635,1821.5
  Bottom Layer w25: C51.1@177.09,1810 210,1810 220,1820 v1@255,1820
NetC53_1: C53.1 D14.1 R69.2 R71.2 R72.2 R73.1 | length 558.1
  Top Layer w20: D14.1@153.31,1495 v1(250,1495) 325,1495 332.91,1487.09 R69.2@385,1487.09 484.41,1487.09 R71.2@485,1486.5 R72.2@560,1486.5 R73.1@635,1486.5
  Bottom Layer w20: C53.1@177.09,1495 v1(250,1495)
NetC54_1: C54.1 R131.2 U3.5 | length 314.5
  Top Layer w10: U3.5@1488.43,1356.22 1488.43,1418.43 v1(1530,1460)
  Bottom Layer w30: v1(1530,1460) 1530.87,1460.87 C54.1@1530.87,1550 1538.5,1557.64 R131.2@1538.5,1650
NetC55_1: C55.1 U2.4 | length 98.3
  Top Layer w15: U2.4@1910,1510.16 v2(1910,1555)
  Bottom Layer w15: C55.1@1910,1501.5 v2(1910,1555)
NetC56_1: C56.1 R136.2 U3.10 | length 264.2
  Top Layer w10: v2(1383,1474) 1405,1452 1405,1424.64 1390,1409.64 U3.10@1390,1356.22
  Bottom Layer w10: R136.2@1256.5,1485 1321.5,1485 C56.1@1325,1481.5 1375.5,1481.5 v2(1383,1474)
NetC56_2: C56.2 R139.2 U3.11 | length 213.7
  Top Layer w10: U3.11@1370.32,1356.22 1370.32,1425.32 v2(1380,1435)
  Bottom Layer w10: R139.2@1256.5,1420 1323.5,1420 C56.2@1325,1418.5 1363.5,1418.5 v2(1380,1435)
NetC57_1: C57.1 D16.1 R78.1 R80.2 R81.2 R82.2 | length 551.1
  Top Layer w20: D16.1@153.31,1170 v1(245,1170) 247.91,1167.09 R80.2@385,1167.09 484.41,1167.09 R81.2@485,1166.5 R82.2@560,1166.5 R78.1@635,1166.5
  Bottom Layer w20: C57.1@177.09,1170 v1(245,1170)
NetC61_1: C61.1 D18.1 R83.1 R94.2 R95.2 R96.2 | length 557.4
  Top Layer w20: D18.1@156.31,812 v2(252,812) ; v2@251,813 v2(252,812) ; 340.59,811.5 340,812.09 ; R83.1@635,811.5 R96.2@560,811.5 559.41,812.09 R94.2@385,812.09 340,812.09 ; v2(252,812) 252.09,812.09 340,812.09
  Bottom Layer w20: C61.1@177.09,815 249,815 v2(252,812)
NetC62_1: C62.1 D21.1 R97.1 R102.2 R107.2 R111.2 | length 560.7
  Top Layer w20: R97.1@658.5,635 R102.2@658.5,560 R107.2@658.5,485 657.91,484.41 R111.2@657.91,385 657.91,257.09 v1(660,255) D21.1@660,153.31
  Bottom Layer w20: C62.1@660,177.09 v1(660,255)
NetC63_1: C63.1 D22.1 R98.1 R103.2 R108.2 R112.2 | length 551.9
  Top Layer w20: R98.1@953.5,635 R103.2@953.5,560 R108.2@953.5,485 952.91,484.41 R112.2@952.91,385 952.91,257.09 v1(970,240) D22.1@970,153.31
  Bottom Layer w20: C63.1@970,177.09 v1(970,240)
NetC64_1: C64.1 D23.1 R99.1 R104.2 R109.2 R113.2 | length 550
  Top Layer w20: D23.1@1267.91,158.22 v1(1267.91,247.09) R113.2@1267.91,385 1267.91,484.41 R109.2@1268.5,485 R104.2@1268.5,560 R99.1@1268.5,635
  Bottom Layer w20: v1(1267.91,247.09) 1275,240 C64.1@1275,177.09
NetC65_1: C65.1 D24.1 R100.1 R105.2 R110.2 R114.2 | length 547.8
  Top Layer w20: D24.1@1607.91,160.39 R114.2@1607.91,385 1607.91,484.41 R110.2@1608.5,485 R105.2@1608.5,560 R100.1@1608.5,635
  Bottom Layer w20: C65.1@1615,177.09 v1@1615,250
  other v1: 1607.91,259
NetD9_1: D9.1 Q1.1 Q1.2 Q1.5 Q1.6 Q1.8 | length 25.6
  Top Layer w10: Q1.5@2182.64,2322 Q1.6@2182.64,2347.59
NetD9_2: D9.2 R47.1 | length 69.5
  Top Layer w10: D9.2@2287.48,2345 2287.48,2279.02 R47.1@2290,2276.5
NetD13_2: D13.2 R58.1 | length 56
  Top Layer w15: R58.1@1896.5,1740 D13.2@1952.52,1740
NetD15_2: D15.2 J11.1
NetD19_2: D19.2 R93.1 | length 58.6
  Top Layer w15: R93.1@2183.5,771 2183.5,715.98 D19.2@2186,713.48
NetD20_1: D20.1 Q2.1 Q2.2 Q2.5 Q2.6 Q2.8
NetD20_2: D20.2 R101.1 | length 75.4
  Top Layer w15: R101.1@2261.5,615 2262.48,614.02 D20.2@2262.48,540
NetJ11_2: J11.2 R138.1 | length 103.3
  Bottom Layer w10: J11.2@2228,1498 J11.2@2230,1500
  Bottom Layer w15: R138.1@2127.5,1498 J11.2@2228,1498
NetR34_2: R34.2 TP3.1 U1.1 | length 163.8
  Top Layer w10: U1.1@1516.5,2449.21 1516.5,2494.28 1523.33,2501.11 TP3.1@1556.33,2501.11 1575.83,2501.11 R34.2@1615.83,2461.11
NetR55_1: R55.1 U1.36 | length 272
  Top Layer w10: U1.36@1477.13,2226.77 1477.13,2165.32 1590,2052.44 R55.1@1590,2001.5
NetR56_1: R56.1 TP7.1 U1.37 | length 329.5
  Top Layer w10: U1.37@1496.81,2226.77 1496.81,2175.63 1561.33,2111.11 1597.44,2075 TP7.1@1660,2075 R56.1@1660,2001.5
NetR79_2: R79.2 R143.1 U3.36 | length 335
  Top Layer w10: U3.36@1527.8,1133.78 1527.8,1181.85 1540,1194.06 1597.94,1194.06 1616.5,1175.5 v2(1698,1175.5) R79.2@1738.5,1135
  Bottom Layer w10: v2@1705.5,1168 R143.1@1738.5,1135
NetR92_1: R92.1 TP18.1 U3.37 | length 281
  Top Layer w10: U3.37@1547.48,1133.78 1547.48,1063.52 1609,1002 1627,1002 TP18.1@1653,976 1659,970 R92.1@1659,909.5
NetR124_2: R124.2 R125.1 TP4.1 | length 146.1
  Bottom Layer w10: TP4.1@1060,2460 1056.5,2463.5 R124.2@1056.5,2530 1059.61,2533.11 R125.1@1129.83,2533.11
NetR134_2: R134.2 R139.1 TP13.1 | length 148.5
  Bottom Layer w10: TP13.1@1125,1345 1121.5,1348.5 R134.2@1121.5,1420 R139.1@1193.5,1420
NetR137_1: R137.1 U2.3 | length 118.2
  Top Layer w15: v2(1990,1560) 2007.24,1542.76 U2.3@2007.24,1507.4
  Bottom Layer w15: R137.1@1990,1501.5 v2(1990,1560)
NetR140_2: R140.2 TP14.1 U3.1 | length 230.9
  Top Layer w10: U3.1@1567.17,1356.22 1567.17,1392.17 1573.5,1398.5 1609.5,1398.5 1648,1360 TP14.1@1685,1360
  Bottom Layer w10: TP14.1@1685,1360 R140.2@1743.5,1360
NetR145_1: R145.1 U4.3 | length 100.4
  Top Layer w15: v2(1885,1023) 1931.84,1023 U4.3@1932.6,1022.24
  Bottom Layer w15: v2(1885,1023) 1885.43,1023.43 R145.1@1937.31,1023.43
REF1: R127.1 R131.1 TP2.1 TP11.1 | length 1358
  Top Layer w10: TP11.1@1604,1715 TP11.1@1601,1718 1672,1789 v1(1701,1789)
  Bottom Layer w10: TP11.1@1601,1718 1601.5,1717.5 R131.1@1601.5,1650 ; v1(1701,1789) 1675,1815 1675,1901 1827,2053 1827,2408 1903,2484 1903,2597 1876,2624 R127.1@1739.5,2624 1739.5,2691.5 TP2.1@1740,2692
SCLK: J11.3 R56.2 R92.2 | length 2051
  Top Layer w10: R92.2@1659,846.5 1695.5,846.5 1698.5,843.5 v2(1700,845) ; R56.2@1660,1938.5 1660,1899 v1(1723,1836)
  Bottom Layer w10: v2(1700,845) 1786,845 1873,932 2190,932 2305,1047 2305,1525 ; v1(1723,1836) 1824,1836 1940,1720 2108,1720 2110,1720
  Bottom Layer w15: 2108,1720 2228,1600 J11.3@2230,1600 2305,1525
SDI: J11.5 R143.2 TP19.1 | length 1285.5
  Top Layer w10: v2(2195,1145) 2235,1145 2300,1210 2300,1689
  Top Layer w15: J11.5@2230,1800 2300,1730 2300,1689
  Bottom Layer w10: TP19.1@1751,1076 1780.5,1076 1801.5,1097 R143.2@1801.5,1135 1840,1135 1888,1087 2007,1087 2065,1145 v2(2195,1145)
SDI_1: R55.2 R76.2 R77.2 R79.1 TP24.1 U3.3 | length 1502.3
  Top Layer w10: U3.3@1527.8,1356.22 1527.8,1275.12 1582.91,1220 TP24.1@1679,1220 R76.2@1743.5,1220 ; v1(1590,1890) R55.2@1590,1938.5 ; R77.2@1743.5,1290 R76.2@1743.5,1220 ; R79.1@1801.5,1135 1743.5,1192.99 R76.2@1743.5,1220
  Bottom Layer w10: v1(1590,1890) 1590,1790.5 1801,1579.5 1801,1471 1780,1450 1634,1450 1604.5,1420.5 1604.5,1331.5 1679,1257 TP24.1@1679,1220
SDO: J11.4 R34.1 R140.1 | length 1758.9
  Top Layer w10: R34.1@1678.83,2461.11 1701.83,2438.11 1894.11,2438.11 v2(1896,2440) ; v1(1915,1620) 1995,1700 2077,1700
  Top Layer w15: 2077,1700 J11.4@2230,1700
  Bottom Layer w10: R140.1@1806.5,1360 1871.75,1425.25 1871.75,1576.75 v1(1915,1620) ; v2(1896,2440) 1896,2385 2156,2125 2156,1818
  Bottom Layer w15: 2156,1818 2156,1774 J11.4@2230,1700
SGND: C9.2 C11.2 C13.2 C15.1 C16.2 C18.2 C19.2 C21.2 C23.2 C24.2 C25.2 C30.2 C31.2 C32.2 C33.2 C34.2 C41.2 C42.2 C43.1 C46.2 C48.2 C49.2 C50.2 C52.2 C54.2 C55.2 C58.2 C59.2 C60.2 D11.2 D13.1 D17.2 D19.1 J11.8 Q1.4 Q1.7 Q2.4 Q2.7 R5.1 R6.1 R7.1 R8.1 R9.1 R11.1 R13.1 R15.1 R17.1 R20.1 R30.1 R32.1 R37.1 R42.1 R45.1 R52.1 R53.1 R59.1 R60.1 R67.2 R71.1 R72.1 R76.1 R81.1 R82.1 R95.1 R96.1 R102.1 R103.1 R104.1 R105.1 R107.1 R108.1 R109.1 R110.1 R115.1 R116.1 R117.1 R118.1 R119.1 R120.1 R121.1 R123.1 R124.1 R126.2 R129.1 R130.1 R132.1 R134.1 R135.1 R141.1 R146.1 R147.1 R148.1 R149.1 R150.1 R151.1 R155.1 R157.1 TP6.1 TP9.1 TP21.1 TP22.1 U1.6 U1.8 U1.28 U1.29 U1.31 U1.32 U1.33 U2.2 U3.6 U3.8 U3.28 U3.29 U3.31 U3.32 U3.33 U4.2 | length 4107.9
  Top Layer w10: v1(1173.33,2331.11) v1(1239.33,2331.11) v1(1295.33,2331.11) ; U1.28@1319.65,2226.77 1319.65,2306.8 ; U1.29@1339.33,2226.77 1339.33,2287.11 1319.65,2306.8 ; v1(1370,1250) v1@1370.32,1249.68 ; U3.28@1370.32,1133.78 v1@1370.32,1249.68 ; U1.31@1378.7,2226.77 1378.7,2306.74 v1(1354.33,2331.11) ; U1.8@1378.7,2449.21 1378.7,2355.48 v1(1354.33,2331.11) ; U3.29@1390,1133.78 1390,1230 v1@1370.32,1249.68 ; U1.32@1398.39,2226.77 1398.39,2311.17 1418.33,2331.11 ; U1.33@1418.07,2226.77 1418.07,2293.07 1435,2310 v1(1460,2310) ; U1.6@1418.07,2449.21 1418.07,2331.37 1418.33,2331.11 ; U3.31@1429.37,1133.78 v1@1429.37,1240 ; U3.8@1429.37,1356.22 v1@1429.37,1250 ; U3.32@1449.06,1133.78 1449.06,1220.31 v1@1429.37,1240 ; U3.33@1468.74,1133.78 1468.74,1203.74 v1(1485,1220) ; U3.6@1468.74,1356.22 1468.74,1266.26 1485,1250 v1(1430,1250) v1@1429.37,1250 ; v1(1295.33,2331.11) 1319.65,2306.8 ; v1(1295.33,2331.11) v1(1354.33,2331.11) ; v1(1354.33,2331.11) 1418.33,2331.11 ; v1@1429.37,1240 v1@1429.37,1250
  Top Layer w15: Q2.7@2118.78,514.41 Q2.4@2151.32,514.41
  Top Layer w20: R45.1@1682.83,2263.11 1722.83,2223.11 v1(1724.33,2223.11) ; R76.1@1806.5,1220 1838.5,1188 v1(1886,1188) ; C25.2@1943.5,1105 1968.81,1079.69 1968.81,1023.43 U4.2@1970,1022.24 ; U2.2@2007.24,1470 2075,1470 v1(2100,1445) ; D13.1@2015,1737.48 v1(2015,1785) ; C34.2@2021.5,450 2080,450 ; v1@2063.04,710 v1(2065,710) D19.1@2117.52,710
  Top Layer w30: C15.1@1525,1611.5 1573.5,1611.5 1605,1580 R67.2@1605,1522.44
  Bottom Layer w20: v1(940,2530) R124.1@993.5,2530 ; v1(940,2595) R123.1@993.5,2595 ; C42.2@1560,2779.13 1677.5,2779.13 ; v1(1890,1355) 1910,1375 C55.2@1910,1438.5
  Bottom Layer w25: v1(1315,1250) v1(1370,1250) v1(1430,1250) 1465,1285 1585,1285 1634.13,1235.87 C59.2@1634.13,1138.4 ; v1(1485,1220) 1552.53,1220 C59.2@1634.13,1138.4 ; C59.2@1634.13,1135 C59.2@1634.13,1138.4
  Bottom Layer w30: R155.1@926.5,2728 v1(926.5,2778.5) ; R157.1@993.5,1600 993.5,1526.5 v1(1010,1510) ; v1(1460,2310) 1503.5,2353.5 R126.2@1600,2353.5 1600,2204.65 C49.2@1598.46,2203.11 ; 1677.5,2779.13 1677.5,2787.5 v1(1700,2810) ; C46.2@1743.13,2521 v1(1834,2521)
  other v1: 2067,365 2021,404 2066,407 2135,450 1740,750 1740,805 2241,833 2277,877 2207,1037 1089,1085 1140,1085 1890,1135 1090,1152 1141,1152 1885,1276 1010,1415 1750,1495 1750,1550 1250,1665 1315,1665 1275,1710 1100,1715 1160,1715 1330,1720 1045,1780 1980,1885 2015,2050 2065,2080 2070,2135 1690,2170 1665,2205 2100,2225 2155,2225 1829,2478 1824,2572 1760,2810 1705,2860 1755,2860
  other v2: 1750,485 1815,485 795,490 860,490 1105,490 1170,490 1405,490 1475,490 1750,540 1810,540 795,555 860,555 1105,555 1170,555 1405,555 1475,555 500,605 565,605 500,665 565,665 495,965 570,965 495,1025 570,1025 481,1287 539,1289 479,1343 540,1343 481,1603 541,1604 482,1661 542,1663 500,1945 570,1945 500,1995 570,1995 483,2269 538,2269 483,2329 543,2329 511,2613.5 556,2613.5 511,2678.5 556,2678.5 506,2963.5 551,2963.5 506,3033.5 551,3033.5 1740,3175 1810,3175 1390,3180 1450,3180 651.5,3185 711.5,3185 1036.5,3185 1111.5,3185 1036.5,3225 1111.5,3225 651.5,3235 711.5,3235 1740,3240 1810,3240 1390,3245 1450,3245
